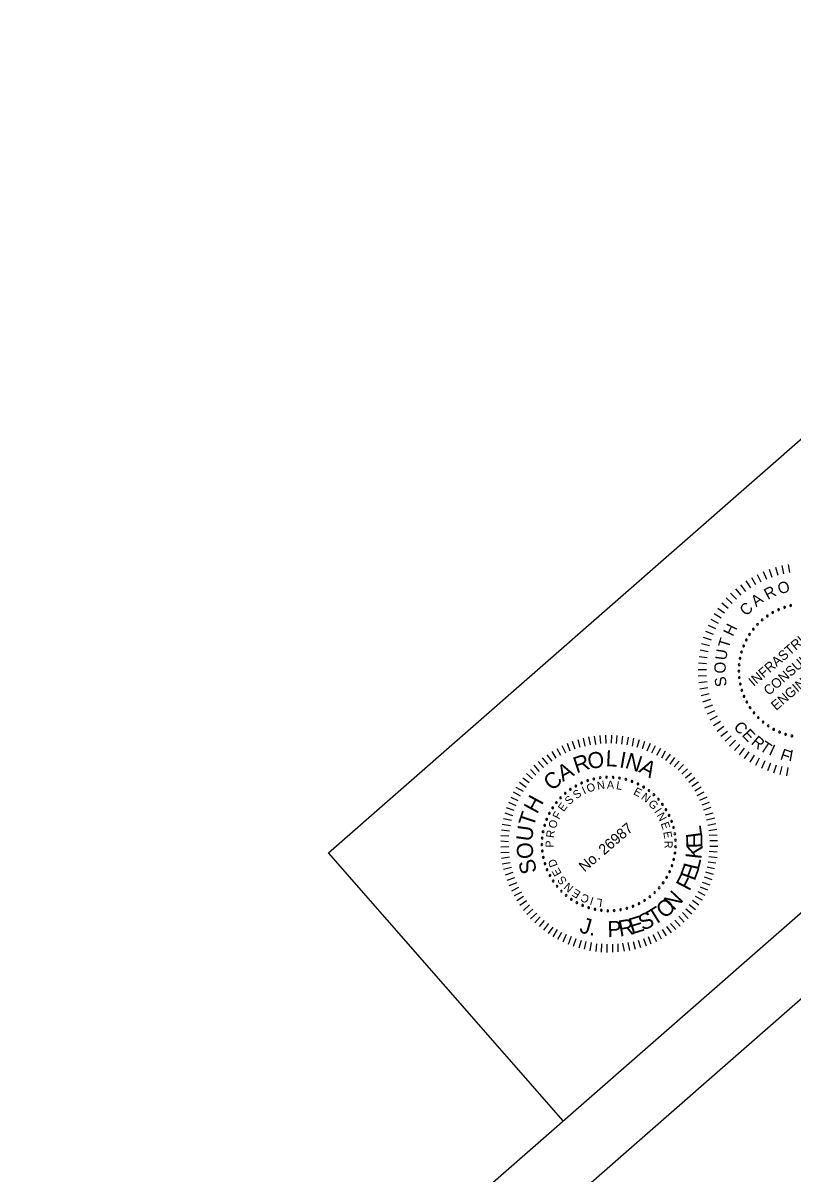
# Model space of a CAD drawing. Extents: x 1970965 to 1971298, y 796258 to 796581.
# Drawn here: x 1971181.2 to 1971228.7, y 796377.5 to 796448.5 of the extents above; entities that cross this region are included whole.
import ezdxf

# ---------------------------------------------------------------- set-up
doc = ezdxf.new("R2010")
doc.units = 0
for name, color, linetype in [('BR_BORDER LINES', 7, 'Continuous'), ('BR_TEXT', 7, 'Continuous'), ('Level 31', 7, 'Continuous')]:
    doc.layers.add(name, color=color, linetype=linetype)

msp = doc.modelspace()

# ---------------------------------------------------------------- linework, layer by layer
at = {"layer": 'BR_BORDER LINES'}
for p, q in [((1971089.346, 796271.087), (1971291.955, 796448.534)), ((1971200.032, 796397.273), (1971232.321, 796425.552)), ((1971214.527, 796380.723), (1971200.032, 796397.273))]:
    msp.add_line(p, q, dxfattribs=at)
at = {"layer": 'BR_TEXT'}
for p, q in [((1971228.027, 796415.017), (1971228.14, 796414.52)), ((1971228.424, 796415.094), (1971228.506, 796414.591)), ((1971226.51, 796414.474), (1971226.739, 796414.019)), ((1971226.876, 796414.644), (1971227.077, 796414.176)), ((1971227.252, 796414.792), (1971227.424, 796414.312)), ((1971227.636, 796414.916), (1971227.779, 796414.427)), ((1971225.483, 796413.834), (1971225.791, 796413.428)), ((1971225.812, 796414.068), (1971226.095, 796413.644)), ((1971226.154, 796414.282), (1971226.411, 796413.842)), ((1971224.589, 796413.018), (1971224.966, 796412.675)), ((1971224.87, 796413.308), (1971225.226, 796412.943)), ((1971225.168, 796413.58), (1971225.501, 796413.194)), ((1971224.083, 796412.389), (1971224.499, 796412.095)), ((1971224.326, 796412.711), (1971224.724, 796412.392)), ((1971223.657, 796411.703), (1971224.105, 796411.462)), ((1971223.859, 796412.052), (1971224.292, 796411.784)), ((1971223.317, 796410.97), (1971223.792, 796410.785)), ((1971223.476, 796411.342), (1971223.938, 796411.128)), ((1971223.069, 796410.202), (1971223.563, 796410.076)), ((1971223.182, 796410.59), (1971223.667, 796410.434)), ((1971222.917, 796409.409), (1971223.422, 796409.344)), ((1971222.981, 796409.808), (1971223.481, 796409.712)), ((1971222.877, 796409.007), (1971223.386, 796408.973)), ((1971222.862, 796408.604), (1971223.372, 796408.601)), ((1971222.872, 796408.2), (1971223.38, 796408.228)), ((1971222.906, 796407.798), (1971223.412, 796407.857)), ((1971222.964, 796407.398), (1971223.466, 796407.488)), ((1971223.047, 796407.003), (1971223.542, 796407.123)), ((1971223.154, 796406.613), (1971223.641, 796406.763)), ((1971223.284, 796406.231), (1971223.761, 796406.41)), ((1971223.438, 796405.857), (1971223.902, 796406.066)), ((1971223.613, 796405.494), (1971224.065, 796405.73)), ((1971223.811, 796405.142), (1971224.247, 796405.405)), ((1971224.03, 796404.802), (1971224.449, 796405.091)), ((1971215.886, 796403.858), (1971215.781, 796404.358)), ((1971216.209, 796403.946), (1971216.119, 796404.44)), ((1971216.537, 796403.975), (1971216.457, 796404.478)), ((1971216.852, 796404.02), (1971216.806, 796404.515)), ((1971217.184, 796404.034), (1971217.168, 796404.546)), ((1971217.506, 796404.049), (1971217.533, 796404.543)), ((1971217.821, 796404.03), (1971217.853, 796404.52)), ((1971218.154, 796403.991), (1971218.221, 796404.492)), ((1971218.486, 796403.942), (1971218.565, 796404.418)), ((1971218.807, 796403.865), (1971218.897, 796404.359)), ((1971224.269, 796404.477), (1971224.67, 796404.791)), ((1971224.528, 796404.166), (1971224.908, 796404.505)), ((1971214.382, 796403.279), (1971214.156, 796403.71)), ((1971214.685, 796403.432), (1971214.461, 796403.882)), ((1971214.963, 796403.562), (1971214.793, 796404.022)), ((1971215.269, 796403.69), (1971215.095, 796404.156)), ((1971215.577, 796403.774), (1971215.453, 796404.255)), ((1971219.094, 796403.804), (1971219.241, 796404.275)), ((1971219.422, 796403.697), (1971219.579, 796404.167)), ((1971219.711, 796403.583), (1971219.916, 796404.05)), ((1971220.012, 796403.453), (1971220.226, 796403.9)), ((1971220.318, 796403.309), (1971220.55, 796403.735)), ((1971224.805, 796403.872), (1971225.164, 796404.233)), ((1971225.099, 796403.596), (1971225.436, 796403.978)), ((1971225.41, 796403.338), (1971225.722, 796403.74)), ((1971213.583, 796402.745), (1971213.257, 796403.144)), ((1971213.84, 796402.94), (1971213.548, 796403.331)), ((1971214.097, 796403.115), (1971213.842, 796403.538)), ((1971220.612, 796403.136), (1971220.844, 796403.571)), ((1971220.863, 796402.972), (1971221.15, 796403.373)), ((1971221.134, 796402.761), (1971221.418, 796403.169)), ((1971221.374, 796402.588), (1971221.693, 796402.944)), ((1971225.735, 796403.099), (1971226.023, 796403.519)), ((1971226.075, 796402.881), (1971226.337, 796403.318)), ((1971226.427, 796402.683), (1971226.662, 796403.136)), ((1971226.791, 796402.508), (1971226.998, 796402.974)), ((1971212.847, 796402.084), (1971212.503, 796402.431)), ((1971213.073, 796402.306), (1971212.737, 796402.696)), ((1971213.314, 796402.541), (1971212.992, 796402.915)), ((1971221.631, 796402.374), (1971221.965, 796402.733)), ((1971221.847, 796402.143), (1971222.212, 796402.457)), ((1971222.078, 796401.907), (1971222.447, 796402.225)), ((1971227.165, 796402.355), (1971227.343, 796402.832)), ((1971227.548, 796402.225), (1971227.696, 796402.713)), ((1971227.937, 796402.119), (1971228.056, 796402.615)), ((1971228.333, 796402.037), (1971228.421, 796402.539)), ((1971212.235, 796401.321), (1971211.834, 796401.619)), ((1971212.431, 796401.599), (1971212.034, 796401.882)), ((1971212.63, 796401.852), (1971212.255, 796402.172)), ((1971222.286, 796401.634), (1971222.66, 796401.937)), ((1971222.478, 796401.391), (1971222.887, 796401.662)), ((1971211.899, 796400.787), (1971211.464, 796401.028)), ((1971212.071, 796401.071), (1971211.635, 796401.303)), ((1971222.651, 796401.105), (1971223.059, 796401.357)), ((1971222.805, 796400.821), (1971223.241, 796401.052)), ((1971211.62, 796400.184), (1971211.167, 796400.383)), ((1971211.754, 796400.481), (1971211.317, 796400.694)), ((1971222.973, 796400.521), (1971223.413, 796400.746)), ((1971223.103, 796400.244), (1971223.563, 796400.414)), ((1971223.221, 796399.938), (1971223.677, 796400.104)), ((1971211.418, 796399.567), (1971210.949, 796399.733)), ((1971211.506, 796399.896), (1971211.037, 796400.062)), ((1971223.31, 796399.625), (1971223.797, 796399.754)), ((1971223.389, 796399.312), (1971223.894, 796399.431)), ((1971211.207, 796398.623), (1971210.719, 796398.674)), ((1971211.274, 796398.945), (1971210.77, 796399.036)), ((1971211.343, 796399.275), (1971210.839, 796399.376)), ((1971223.472, 796398.994), (1971223.961, 796399.08)), ((1971223.53, 796398.654), (1971224.013, 796398.735)), ((1971211.158, 796397.965), (1971210.673, 796397.991)), ((1971211.173, 796398.305), (1971210.674, 796398.337)), ((1971223.547, 796398.361), (1971224.036, 796398.393)), ((1971223.576, 796398.033), (1971224.063, 796398.035)), ((1971211.173, 796397.642), (1971210.669, 796397.617)), ((1971211.191, 796397.305), (1971210.684, 796397.285)), ((1971223.547, 796397.382), (1971224.045, 796397.331)), ((1971223.584, 796397.687), (1971224.085, 796397.683)), ((1971211.214, 796397.016), (1971210.716, 796396.932)), ((1971211.26, 796396.667), (1971210.767, 796396.578)), ((1971223.474, 796396.731), (1971223.965, 796396.655)), ((1971223.532, 796397.053), (1971224.034, 796396.996)), ((1971211.336, 796396.369), (1971210.849, 796396.24)), ((1971211.424, 796396.056), (1971210.946, 796395.907)), ((1971223.32, 796396.1), (1971223.796, 796395.957)), ((1971223.411, 796396.405), (1971223.88, 796396.302)), ((1971211.522, 796395.732), (1971211.056, 796395.558)), ((1971211.66, 796395.425), (1971211.169, 796395.238)), ((1971211.775, 796395.144), (1971211.329, 796394.914)), ((1971222.979, 796395.181), (1971223.436, 796394.986)), ((1971223.108, 796395.473), (1971223.586, 796395.296)), ((1971223.234, 796395.79), (1971223.708, 796395.628)), ((1971211.953, 796394.853), (1971211.493, 796394.62)), ((1971212.079, 796394.581), (1971211.669, 796394.31)), ((1971222.673, 796394.61), (1971223.108, 796394.368)), ((1971222.85, 796394.889), (1971223.276, 796394.657)), ((1971212.268, 796394.309), (1971211.858, 796394.028)), ((1971212.458, 796394.056), (1971212.068, 796393.72)), ((1971212.663, 796393.798), (1971212.283, 796393.471)), ((1971222.112, 796393.809), (1971222.48, 796393.51)), ((1971222.299, 796394.088), (1971222.705, 796393.785)), ((1971222.512, 796394.344), (1971222.915, 796394.066)), ((1971212.897, 796393.547), (1971212.516, 796393.2)), ((1971213.115, 796393.326), (1971212.78, 796392.957)), ((1971213.356, 796393.099), (1971213.036, 796392.723)), ((1971221.428, 796393.12), (1971221.746, 796392.751)), ((1971221.67, 796393.356), (1971222.003, 796392.99)), ((1971221.901, 796393.582), (1971222.249, 796393.23)), ((1971213.624, 796392.913), (1971213.316, 796392.503)), ((1971213.885, 796392.694), (1971213.592, 796392.288)), ((1971214.151, 796392.533), (1971213.888, 796392.081)), ((1971214.425, 796392.362), (1971214.184, 796391.927)), ((1971220.348, 796392.408), (1971220.582, 796391.957)), ((1971220.646, 796392.546), (1971220.893, 796392.143)), ((1971220.907, 796392.726), (1971221.204, 796392.329)), ((1971221.16, 796392.917), (1971221.483, 796392.542)), ((1971214.722, 796392.228), (1971214.517, 796391.761)), ((1971215.014, 796392.099), (1971214.828, 796391.621)), ((1971215.311, 796391.965), (1971215.149, 796391.49)), ((1971215.649, 796391.867), (1971215.487, 796391.392)), ((1971215.932, 796391.802), (1971215.823, 796391.318)), ((1971216.262, 796391.733), (1971216.167, 796391.234)), ((1971216.588, 796391.66), (1971216.538, 796391.182)), ((1971216.899, 796391.657), (1971216.866, 796391.148)), ((1971217.233, 796391.627), (1971217.22, 796391.127)), ((1971217.565, 796391.641), (1971217.567, 796391.144)), ((1971217.902, 796391.66), (1971217.914, 796391.163)), ((1971218.202, 796391.691), (1971218.287, 796391.213)), ((1971218.531, 796391.74), (1971218.626, 796391.251)), ((1971218.842, 796391.799), (1971218.972, 796391.322)), ((1971219.156, 796391.888), (1971219.301, 796391.424)), ((1971219.479, 796391.985), (1971219.645, 796391.53)), ((1971219.781, 796392.119), (1971219.951, 796391.648)), ((1971220.063, 796392.234), (1971220.288, 796391.803))]:
    msp.add_line(p, q, dxfattribs=at)
for centre, start, end in [((1971227.472, 796412.122), 29.66193, 209.66193), ((1971227.828, 796412.302), 24.12347, 204.12347), ((1971227.828, 796412.302), 204.12347, 24.12347), ((1971228.199, 796412.446), 18.58501, 198.58501), ((1971228.199, 796412.446), 198.58501, 18.58501), ((1971228.583, 796412.554), 13.04655, 193.04655), ((1971228.583, 796412.554), 193.04655, 13.04655), ((1971226.82, 796411.665), 40.73885, 220.73885), ((1971226.82, 796411.665), 220.73885, 40.73885), ((1971227.135, 796411.909), 35.20039, 215.20039), ((1971227.135, 796411.909), 215.20039, 35.20039), ((1971227.472, 796412.122), 209.66193, 29.66193), ((1971226.037, 796410.766), 57.35424, 237.35424), ((1971226.037, 796410.766), 237.35424, 57.35424), ((1971226.269, 796411.09), 51.81578, 231.81578), ((1971226.269, 796411.09), 231.81578, 51.81578), ((1971226.53, 796411.391), 46.27732, 226.27732), ((1971226.53, 796411.391), 226.27732, 46.27732), ((1971225.673, 796410.058), 68.43116, 248.43116), ((1971225.673, 796410.058), 248.43116, 68.43116), ((1971225.838, 796410.42), 62.8927, 242.8927), ((1971225.838, 796410.42), 242.8927, 62.8927), ((1971225.451, 796409.293), 79.50808, 259.50808), ((1971225.451, 796409.293), 259.50808, 79.50808), ((1971225.543, 796409.68), 73.96962, 253.96962), ((1971225.543, 796409.68), 253.96962, 73.96962), ((1971225.397, 796408.898), 85.04655, 265.04655), ((1971225.397, 796408.898), 265.04655, 85.04655), ((1971225.381, 796408.499), 90.58501, 270.58501), ((1971225.403, 796408.101), 96.12347, 276.12347), ((1971225.381, 796408.499), 270.58501, 90.58501), ((1971225.403, 796408.101), 276.12347, 96.12347), ((1971225.464, 796407.707), 101.66193, 281.66193), ((1971225.464, 796407.707), 281.66193, 101.66193), ((1971225.563, 796407.321), 107.20039, 287.20039), ((1971225.563, 796407.321), 287.20039, 107.20039), ((1971225.698, 796406.946), 112.73885, 292.73885), ((1971225.698, 796406.946), 292.73885, 112.73885), ((1971225.869, 796406.586), 118.27732, 298.27732), ((1971225.869, 796406.586), 298.27732, 118.27732), ((1971226.074, 796406.244), 123.81578, 303.81578), ((1971226.074, 796406.244), 303.81578, 123.81578), ((1971226.311, 796405.924), 129.35424, 309.35424), ((1971226.311, 796405.924), 309.35424, 129.35424), ((1971226.578, 796405.627), 134.8927, 314.8927), ((1971226.578, 796405.627), 314.8927, 134.8927), ((1971226.872, 796405.358), 140.43116, 320.43116), ((1971226.872, 796405.358), 320.43116, 140.43116), ((1971227.191, 796405.119), 145.96962, 325.96962), ((1971227.191, 796405.119), 325.96962, 145.96962), ((1971227.531, 796404.911), 151.50808, 331.50808), ((1971227.531, 796404.911), 331.50808, 151.50808), ((1971227.89, 796404.738), 157.04655, 337.04655), ((1971227.89, 796404.738), 337.04655, 157.04655), ((1971228.264, 796404.599), 162.58501, 342.58501), ((1971228.264, 796404.599), 342.58501, 162.58501), ((1971228.649, 796404.498), 168.12347, 348.12347), ((1971228.649, 796404.498), 348.12347, 168.12347), ((1971215.666, 796401.591), 24.12347, 204.12347), ((1971215.666, 796401.591), 204.12347, 24.12347), ((1971216.038, 796401.736), 18.58501, 198.58501), ((1971216.038, 796401.736), 198.58501, 18.58501), ((1971216.421, 796401.843), 13.04655, 193.04655), ((1971216.421, 796401.843), 193.04655, 13.04655), ((1971216.814, 796401.914), 7.50808, 187.50808), ((1971216.814, 796401.914), 187.50808, 7.50808), ((1971217.211, 796401.946), 1.96962, 181.96962), ((1971217.211, 796401.946), 181.96962, 1.96962), ((1971217.61, 796401.94), 356.43116, 176.43116), ((1971217.61, 796401.94), 176.43116, 356.43116), ((1971218.006, 796401.895), 170.8927, 350.8927), ((1971218.006, 796401.895), 350.8927, 170.8927), ((1971218.396, 796401.812), 165.35424, 345.35424), ((1971218.396, 796401.812), 345.35424, 165.35424), ((1971218.776, 796401.692), 159.81578, 339.81578), ((1971218.776, 796401.692), 339.81578, 159.81578), ((1971219.143, 796401.536), 154.27732, 334.27732), ((1971219.143, 796401.536), 334.27732, 154.27732), ((1971214.659, 796400.954), 40.73885, 220.73885), ((1971214.659, 796400.954), 220.73885, 40.73885), ((1971214.973, 796401.198), 35.20039, 215.20039), ((1971214.973, 796401.198), 215.20039, 35.20039), ((1971215.31, 796401.412), 29.66193, 209.66193), ((1971215.31, 796401.412), 209.66193, 29.66193), ((1971219.493, 796401.345), 148.73885, 328.73885), ((1971219.493, 796401.345), 328.73885, 148.73885), ((1971219.823, 796401.121), 143.20039, 323.20039), ((1971219.823, 796401.121), 323.20039, 143.20039), ((1971220.129, 796400.867), 137.66193, 317.66193), ((1971220.129, 796400.867), 317.66193, 137.66193), ((1971213.875, 796400.055), 57.35424, 237.35424), ((1971213.875, 796400.055), 237.35424, 57.35424), ((1971214.107, 796400.379), 51.81578, 231.81578), ((1971214.107, 796400.379), 231.81578, 51.81578), ((1971214.369, 796400.68), 46.27732, 226.27732), ((1971214.369, 796400.68), 226.27732, 46.27732), ((1971220.41, 796400.584), 132.12347, 312.12347), ((1971220.41, 796400.584), 312.12347, 132.12347), ((1971220.662, 796400.275), 126.58501, 306.58501), ((1971220.662, 796400.275), 306.58501, 126.58501), ((1971213.511, 796399.347), 68.43116, 248.43116), ((1971213.511, 796399.347), 248.43116, 68.43116), ((1971213.676, 796399.71), 62.8927, 242.8927), ((1971213.676, 796399.71), 242.8927, 62.8927), ((1971220.884, 796399.943), 121.04655, 301.04655), ((1971220.884, 796399.943), 301.04655, 121.04655), ((1971221.072, 796399.592), 115.50808, 295.50808), ((1971221.072, 796399.592), 295.50808, 115.50808), ((1971213.382, 796398.97), 73.96962, 253.96962), ((1971213.382, 796398.97), 253.96962, 73.96962), ((1971221.225, 796399.224), 109.96962, 289.96962), ((1971221.225, 796399.224), 289.96962, 109.96962), ((1971221.342, 796398.843), 104.43116, 284.43116), ((1971221.342, 796398.843), 284.43116, 104.43116), ((1971213.235, 796398.187), 85.04655, 265.04655), ((1971213.235, 796398.187), 265.04655, 85.04655), ((1971213.29, 796398.582), 79.50808, 259.50808), ((1971213.29, 796398.582), 259.50808, 79.50808), ((1971221.422, 796398.452), 98.8927, 278.8927), ((1971221.464, 796398.056), 93.35424, 273.35424), ((1971221.422, 796398.452), 278.8927, 98.8927), ((1971221.464, 796398.056), 273.35424, 93.35424), ((1971213.219, 796397.789), 90.58501, 270.58501), ((1971213.242, 796397.391), 96.12347, 276.12347), ((1971213.219, 796397.789), 270.58501, 90.58501), ((1971213.242, 796397.391), 276.12347, 96.12347), ((1971221.432, 796397.26), 82.27732, 262.27732), ((1971221.467, 796397.657), 87.81578, 267.81578), ((1971221.432, 796397.26), 262.27732, 82.27732), ((1971221.467, 796397.657), 267.81578, 87.81578), ((1971213.303, 796396.997), 101.66193, 281.66193), ((1971213.303, 796396.997), 281.66193, 101.66193), ((1971213.401, 796396.61), 107.20039, 287.20039), ((1971213.401, 796396.61), 287.20039, 107.20039), ((1971221.248, 796396.485), 71.20039, 251.20039), ((1971221.248, 796396.485), 251.20039, 71.20039), ((1971221.359, 796396.868), 76.73885, 256.73885), ((1971221.359, 796396.868), 256.73885, 76.73885), ((1971213.537, 796396.235), 112.73885, 292.73885), ((1971213.537, 796396.235), 292.73885, 112.73885), ((1971213.708, 796395.875), 118.27732, 298.27732), ((1971213.708, 796395.875), 298.27732, 118.27732), ((1971221.1, 796396.115), 65.66193, 245.66193), ((1971221.1, 796396.115), 245.66193, 65.66193), ((1971213.913, 796395.533), 123.81578, 303.81578), ((1971213.913, 796395.533), 303.81578, 123.81578), ((1971214.15, 796395.213), 129.35424, 309.35424), ((1971214.15, 796395.213), 309.35424, 129.35424), ((1971220.455, 796395.112), 49.04655, 229.04655), ((1971220.455, 796395.112), 229.04655, 49.04655), ((1971220.702, 796395.425), 54.58501, 234.58501), ((1971220.702, 796395.425), 234.58501, 54.58501), ((1971220.918, 796395.76), 60.12347, 240.12347), ((1971220.918, 796395.76), 240.12347, 60.12347), ((1971214.416, 796394.916), 134.8927, 314.8927), ((1971214.416, 796394.916), 314.8927, 134.8927), ((1971214.71, 796394.647), 140.43116, 320.43116), ((1971214.71, 796394.647), 320.43116, 140.43116), ((1971215.029, 796394.408), 145.96962, 325.96962), ((1971215.029, 796394.408), 325.96962, 145.96962), ((1971219.877, 796394.565), 37.96962, 217.96962), ((1971219.877, 796394.565), 217.96962, 37.96962), ((1971220.179, 796394.825), 43.50808, 223.50808), ((1971220.179, 796394.825), 223.50808, 43.50808), ((1971215.37, 796394.2), 151.50808, 331.50808), ((1971215.37, 796394.2), 331.50808, 151.50808), ((1971215.728, 796394.027), 157.04655, 337.04655), ((1971215.728, 796394.027), 337.04655, 157.04655), ((1971216.102, 796393.888), 162.58501, 342.58501), ((1971216.102, 796393.888), 342.58501, 162.58501), ((1971216.488, 796393.787), 168.12347, 348.12347), ((1971216.488, 796393.787), 348.12347, 168.12347), ((1971216.881, 796393.723), 353.66193, 173.66193), ((1971216.881, 796393.723), 173.66193, 353.66193), ((1971217.279, 796393.697), 359.20039, 179.20039), ((1971217.279, 796393.697), 179.20039, 359.20039), ((1971217.677, 796393.71), 4.73885, 184.73885), ((1971217.677, 796393.71), 184.73885, 4.73885), ((1971218.073, 796393.762), 10.27732, 190.27732), ((1971218.073, 796393.762), 190.27732, 10.27732), ((1971218.461, 796393.851), 15.81578, 195.81578), ((1971218.461, 796393.851), 195.81578, 15.81578), ((1971218.839, 796393.977), 21.35424, 201.35424), ((1971218.839, 796393.977), 201.35424, 21.35424), ((1971219.204, 796394.139), 26.8927, 206.8927), ((1971219.204, 796394.139), 206.8927, 26.8927), ((1971219.55, 796394.336), 32.43116, 212.43116), ((1971219.55, 796394.336), 212.43116, 32.43116)]:
    msp.add_arc(centre, 0.0561, start, end, dxfattribs=at)
at = {"layer": 'Level 31'}
msp.add_line((1971080.947, 796258.416), (1971297.603, 796448.164), dxfattribs=at)

# ---------------------------------------------------------------- texts
at = {"layer": 'BR_TEXT'}
for s, height, rotation, p in [('R', 0.698, 27.88009, (1971227.166, 796412.888)), ('O', 0.698, 18.85007, (1971227.911, 796413.223)), ('A', 0.698, 36.91012, (1971226.449, 796412.44)), ('C', 0.698, 45.94014, (1971225.846, 796411.86)), ('INFRASTRUCTURE', 0.59817, 40.73885, (1971226.297, 796407.523)), ('H', 0.698, 64.00019, (1971225.006, 796410.599)), ('CONSULTING &', 0.59817, 40.73885, (1971227.223, 796406.967)), ('T', 0.698, 73.03022, (1971224.747, 796409.865)), ('U', 0.698, 82.06024, (1971224.601, 796409.141)), ('ENGINEERING,', 0.59817, 40.73885, (1971227.682, 796406.035)), ('O', 0.698, 91.09027, (1971224.573, 796408.36)), ('S', 0.698, 100.12029, (1971224.651, 796407.598)), ('C', 0.698, 308.23707, (1971225.021, 796405.051)), ('E', 0.698, 314.23707, (1971225.53, 796404.523)), ('R', 0.698, 320.23707, (1971226.093, 796404.035)), ('T', 0.698, 326.23707, (1971226.613, 796403.652)), ('I', 0.698, 334.98329, (1971227.177, 796403.369)), ('F', 0.698, 340.98329, (1971227.879, 796403.068)), ('R', 0.993, 18.64642, (1971215.35, 796402.182)), ('O', 0.991, 7.79891, (1971216.099, 796402.447)), ('L', 0.993, 357.16082, (1971217.134, 796402.632)), ('I', 0.993, 349.8733, (1971217.955, 796402.561)), ('N', 0.993, 341.91567, (1971218.294, 796402.546)), ('A', 0.993, 330.69123, (1971219.141, 796402.298)), ('I', 0.698, 349.73885, (1971228.416, 796402.966)), ('C', 0.993, 40.76025, (1971213.838, 796401.06)), ('A', 0.993, 29.41015, (1971214.504, 796401.652)), ('O', 0.498, 19.6512, (1971216.076, 796400.99)), ('N', 0.498, 9.41617, (1971216.661, 796401.168)), ('A', 0.498, 359.869, (1971217.226, 796401.238)), ('L', 0.498, 350.66663, (1971217.775, 796401.216)), ('H', 0.993, 61.57573, (1971212.915, 796399.631)), ('S', 0.498, 33.87283, (1971215.335, 796400.577)), ('I', 0.498, 24.32565, (1971215.821, 796400.875)), ('E', 0.498, 332.26102, (1971218.828, 796400.911)), ('N', 0.498, 323.05866, (1971219.304, 796400.637)), ('E', 0.498, 52.62237, (1971214.555, 796399.779)), ('S', 0.498, 43.42, (1971214.905, 796400.203)), ('G', 0.498, 313.51148, (1971219.745, 796400.276)), ('T', 0.993, 71.71123, (1971212.689, 796398.822)), ('F', 0.498, 61.82473, (1971214.277, 796399.305)), ('I', 0.498, 303.62038, (1971220.132, 796399.83)), ('N', 0.498, 298.94593, (1971220.287, 796399.597)), ('U', 0.993, 82.01427, (1971212.594, 796397.944)), ('O', 0.498, 72.05976, (1971214.062, 796398.733)), ('No. 26987', 0.654, 40.73885, (1971215.844, 796396.063)), ('E', 0.498, 289.39875, (1971220.542, 796399.087)), ('L', 0.988, 97.63676, (1971223.119, 796398.273)), ('P', 0.498, 91.15411, (1971213.943, 796397.603)), ('R', 0.498, 81.60693, (1971213.955, 796398.173)), ('E', 0.498, 280.19639, (1971220.705, 796398.562)), ('R', 0.498, 270.99403, (1971220.781, 796398.018)), ('E', 0.988, 90.57592, (1971223.13, 796397.563)), ('O', 0.993, 93.23872, (1971212.693, 796396.926)), ('K', 0.988, 83.51509, (1971223.054, 796396.857)), ('S', 0.991, 104.46316, (1971212.924, 796396.111)), ('D', 0.498, 110.24846, (1971214.2, 796396.497)), ('E', 0.988, 69.39342, (1971222.645, 796395.499)), ('L', 0.988, 76.45425, (1971222.891, 796396.165)), ('E', 0.498, 119.45083, (1971214.452, 796396.008)), ('S', 0.498, 128.998, (1971214.792, 796395.55)), ('F', 0.988, 62.33259, (1971222.319, 796394.868)), ('N', 0.498, 138.54518, (1971215.203, 796395.156)), ('E', 0.498, 147.74754, (1971215.656, 796394.845)), ('C', 0.498, 157.63864, (1971216.192, 796394.596)), ('I', 0.498, 162.31309, (1971216.458, 796394.511)), ('L', 0.498, 171.17153, (1971216.978, 796394.412)), ('N', 0.988, 47.03411, (1971221.362, 796393.667)), ('T', 0.988, 31.6737, (1971220.117, 796392.758)), ('O', 0.988, 39.35391, (1971220.77, 796393.171)), ('J', 0.988, 344.16791, (1971215.486, 796392.377)), ('P', 0.988, 2.3155, (1971217.278, 796392.062)), ('R', 0.988, 9.74795, (1971218.024, 796392.098)), ('E', 0.988, 17.18041, (1971218.76, 796392.231)), ('S', 0.988, 24.24124, (1971219.438, 796392.445)), ('.', 0.988, 350.60938, (1971216.109, 796392.2))]:
    msp.add_text(s, height=height, rotation=rotation, dxfattribs=at).set_placement(p)

doc.saveas('drawing.dxf')
